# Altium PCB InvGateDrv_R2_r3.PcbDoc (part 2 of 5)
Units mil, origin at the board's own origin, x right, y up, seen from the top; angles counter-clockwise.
Board outline 6245 x 2850 mil, 4 copper layers (Top Layer, Power, Ground, Bottom Layer), stack 104.204 mil thick; 409 components, 181 nets, 1050 pads, 683 vias.
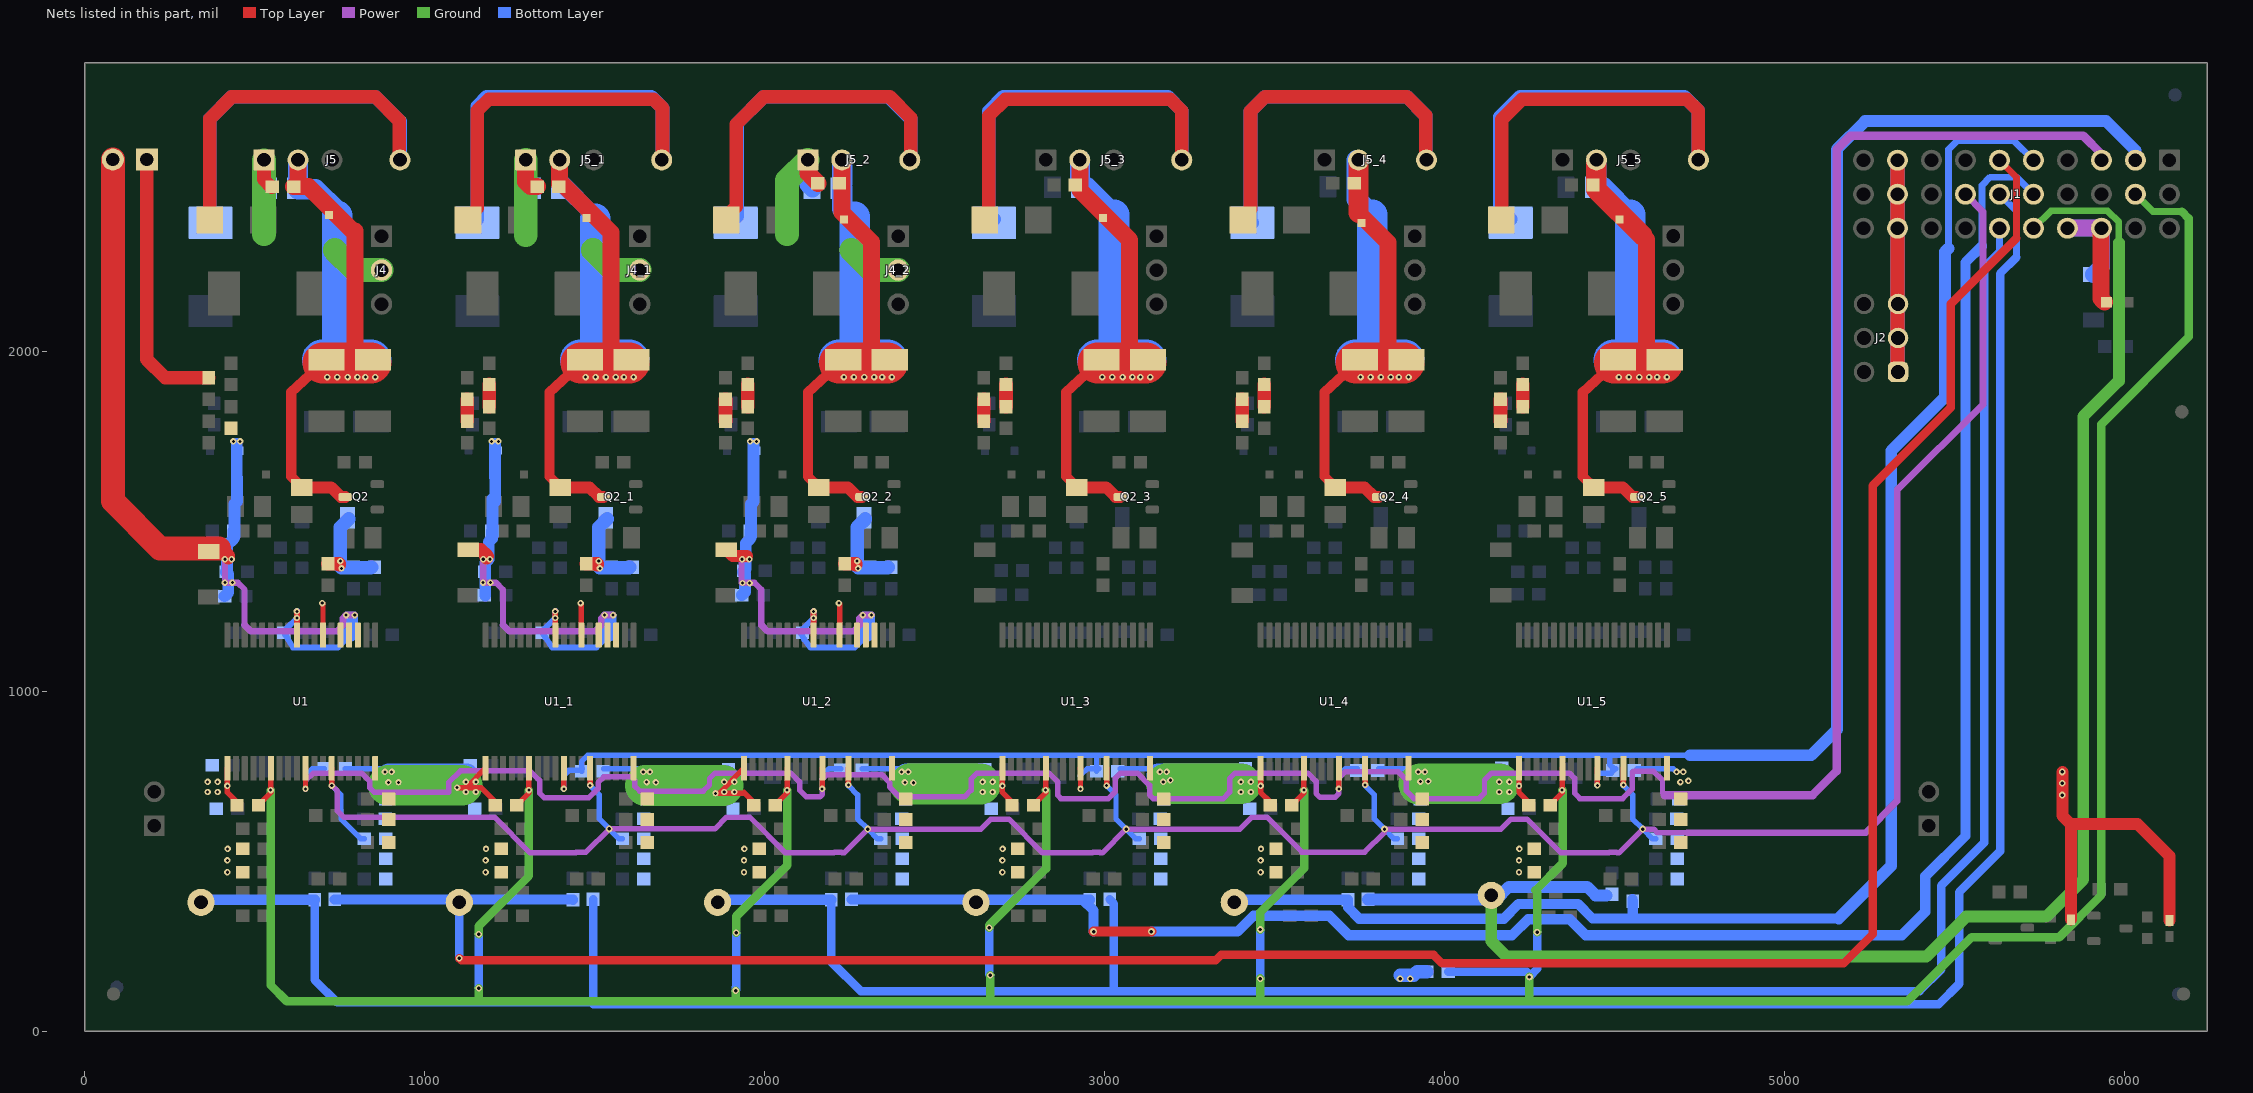
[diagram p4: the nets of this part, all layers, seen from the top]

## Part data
C1: library part CMP-0008658-2, "CAP, CERM, 10 uF, 50 V, +/- 10%, X5R, 1206", Cap_Case=1206_180, Manufacturer=TDK, Supplier Part Number 1=445-5998-1-ND, TempCo=X5R, Tolerance_%=10%, Value1="0.002229 ohm", Value2=50V, ValueDisplayed=10uF
C2 C2_1 C2_2 C2_3 C2_4 C2_5: library part CMP-0007442-5, "CAP, CERM, 220 pF, 50 V, +/- 10%, X7R, 0603", Cap_Case=0603, Manufacturer=MuRata, Supplier Part Number 1=490-1483-1-ND, TempCo=X7R, Tolerance_%=10%, Value1=Unknown, Value2=50V, ValueDisplayed=220pF
C3 C3_1 C3_2 C3_3 C3_4 C3_5 C4 C4_1 C4_2 C4_3 C4_4 C4_5: library part CMP-0008802-2, "CAP, CERM, 10 uF, 50 V, +/- 10%, X7R, 1206", Cap_Case=1206, Manufacturer=Samsung, Supplier Part Number 1=1276-6767-1-ND, TempCo=X7R, Tolerance_%=10%, Value1=Unknown, Value2=50V, ValueDisplayed=10uF
C5 C5_1 C5_2 C5_3 C5_4 C5_5: library part CMP-0007433-4, "CAP, CERM, 0.01 uF, 50 V, +/- 10%, X7R, 0603", Cap_Case=0603, Manufacturer=MuRata, Supplier Part Number 1=490-1512-1-ND, TempCo=X7R, Tolerance_%=10%, Value1=Unknown, Value2=50V, ValueDisplayed=0.01uF
C6 C6_1 C6_2 C6_3 C6_4 C6_5: library part CMP-0007137-5, "CAP, CERM, 1 uF, 16 V, +/- 20%, X7R, AEC-Q200 Grade 1, 0603", Cap_Case=0603, Manufacturer=MuRata, TempCo=X7R, Tolerance_%=20%, Value1=Unknown, Value2=16V, ValueDisplayed=1uF
C7 C7_1 C7_2 C7_3 C7_4 C7_5 C31 C31_1 C31_2 C31_3 C31_4 C31_5: library part CMP-0007106-4, "CAP, CERM, 0.1 uF, 16 V, +/- 10%, X7R, AEC-Q200 Grade 1, 0603", Cap_Case=0603, Manufacturer=TDK, Supplier Part Number 1=445-8136-1-ND, TempCo=X7R, Tolerance_%=10%, Value1=Unknown, Value2=16V, ValueDisplayed=0.1uF
C8 C8_1 C8_2 C8_3 C8_4 C8_5 C9 C9_1 C9_2 C9_3 C9_4 C9_5 C10 C10_1 C10_2 C10_3 C10_4 C10_5 C18 C18_1 C18_2 C18_3 C18_4 C18_5 C19 C19_1 C19_2 C19_3 C19_4 C19_5 C20 C20_1 C20_2 C20_3 C20_4 C20_5 C21 C21_1 C21_2 C21_3 C21_4 C21_5 C22 C22_1 C22_2 C22_3 C22_4 C22_5 C23 C23_1 C23_2 C23_3 C23_4 C23_5 C24 C24_1 C24_2 C24_3 C24_4 C24_5 C25 C25_1 C25_2 C25_3 C25_4 C25_5 C26 C26_1 C26_2 C26_3 C26_4 C26_5: library part CMP-0750041-1, "CAP, CERM, 100 pF, 50 V,+/- 5%, C0G/NP0, AEC-Q200 Grade 1, 0603", Cap_Case=0603, Manufacturer=MuRata, TempCo=C0G/NP0, Tolerance_%=5%, Value2=50V, ValueDisplayed=100pF
C11 C11_1 C11_2 C11_3 C11_4 C11_5 C13 C13_1 C13_2 C13_3 C13_4 C13_5 C15 C15_1 C15_2 C15_3 C15_4 C15_5 C29 C29_1 C29_2 C29_3 C29_4 C29_5: library part CMP-0007010-5, "CAP, CERM, 0.1 uF, 50 V, +/- 10%, X5R, 0603", Cap_Case=0603, Manufacturer=TDK, Supplier Part Number 1=445-7456-1-ND, TempCo=X5R, Tolerance_%=10%, Value1="0.0296 ohm", Value2=50V, ValueDisplayed=0.1uF
C12 C12_1 C12_2 C12_3 C12_4 C12_5 C14 C14_1 C14_2 C14_3 C14_4 C14_5 C17 C17_1 C17_2 C17_3 C17_4 C17_5 C30 C30_1 C30_2 C30_3 C30_4 C30_5: library part CMP-0007067-4, "CAP, CERM, 1 uF, 35 V, +/- 10%, X7R, AEC-Q200 Grade 1, 0603", Cap_Case=0603, Manufacturer=TDK, Supplier Part Number 1=445-174215-1-ND, TempCo=X7R, Tolerance_%=10%, Value1="0.005522 ohm", Value2=35V, ValueDisplayed=1uF
C16 C16_1 C16_2 C16_3 C16_4 C16_5: library part CMP-0007725-2, "CAP, CERM, 0.1 uF, 50 V, +/- 10%, X7R, AEC-Q200 Grade 0, 0805", Cap_Case=0805, Manufacturer=Kemet, Supplier Part Number 1=399-6928-1-ND, TempCo=X7R, Tolerance_%=10%, Value1=Unknown, Value2=50V, ValueDisplayed=0.1uF
C27 C27_1 C27_2 C27_3 C27_4 C27_5 C28 C28_1 C28_2 C28_3 C28_4 C28_5: library part CMP-0007112-4, "CAP, CERM, 4.7 uF, 6.3 V, +/- 10%, X7R, 0603", Cap_Case=0603, Manufacturer=Samsung, Supplier Part Number 1=1276-2087-1-ND, TempCo=X7R, Tolerance_%=10%, Value1=Unknown, Value2=6.3V, ValueDisplayed=4.7uF
D1 D13: library part CMP-0002947-3, "LED, Red, SMD", Color=Red, Manufacturer="Wurth Elektronik", Power_TotalModule=72mW, Value1=0.072W, Value2=2V
D2: library part CMP-0002905-2, "LED, Green, SMD", Color=Green, Manufacturer="Wurth Elektronik", Value1=W, Value2=3.2V
D3 D3_1 D3_2 D3_3 D3_4 D3_5: library part CMP-0077081-2, "Diode, Ultrafast, 1200 V, 1 A, SMA", Manufacturer=STMicroelectronics, Value1=1A, Value2=1.9V
D5 D5_1 D5_2 D5_3 D5_4 D5_5 D10 D10_1 D10_2 D10_3 D10_4 D10_5: library part CMP-0028458-2, "Diode, Schottky, 30 V, 0.2 A, SOD-323", Manufacturer="Diodes Inc.", Value1=0.2A, Value2=0.7V
D7 D7_1 D7_2 D7_3 D7_4 D7_5 D8 D8_1 D8_2 D8_3 D8_4 D8_5: library part CMP-0088475-1, "486V Clamp 3.1A Ipp Tvs Diode Surface Mount DO-214AB (SMCJ)", Breakdown Voltage=335V, Clamping Voltage=486V, Digikey Part Number=SMCJ300ALFCT-ND, Manufacturer="Littelfuse Inc", Mouser Part Number=576-SMCJ300A, Operating Temperature Range="-65°C to +150°C"
D9 D9_1 D9_2 D9_3 D9_4 D9_5: library part CMP-0005831-4, "Diode, Zener, 12 V, 200 mW, SOD-323", Manufacturer="Diodes Inc.", Power_W=200mW, Value1=0.2W
FID1 FID2 FID3 FID4 FID5 FID6: library part CMP-0077181-1, "Fiducial mark.  There is nothing to buy or mount.", Manufacturer=N/A
"High Voltage1" "High Voltage2": library part CMP-0074835-1, "IEC 61010-1 High Voltage Warning"
J1: library part CMP-0088701-1, "Conn Unshrouded Header HDR 30 POS 2.54mm Solder RA Thru-Hole Automotive Bulk", Current_A=6.3A, Digikey Part Number=TSW-110-08-G-T-RA-ND, Manufacturer=Samtec, Mouser Part Number=200-TSW11008GTRA, Operating Temperature Range="-55°C to +125°C", Voltage_V=450V
J2: library part CMP-0082513-1, "Receptacle, 2.54mm, 3x2, Gold, TH", Color=Black, Current_A=3A, Manufacturer="Sullins Connector Solutions", Supplier Part Number 1=S7106-ND, Voltage_V=250V
J3 J6: library part CMP-0055684-1, "Receptacle, 2.54mm, 2x1, Gold, TH", Color=Black, Current_A=6.3A, Manufacturer=Samtec, Supplier Part Number 1=SAM1198-02-ND
J4 J4_1 J4_2 J4_3 J4_4 J4_5: library part CMP-0054646-1, "Receptacle, 100mil, 3x1, Gold, TH", Manufacturer="Sullins Connector Solutions", Supplier Part Number 1=S7036-ND
J5 J5_1 J5_3 J5_5: library part CMP-0088430-1, "THROUGH-HOLE .025\" SQ POST HEADER", Digikey Part Number=TSW-105-08-G-S-RA-004-ND, Manufacturer=Samtec, Mouser Part Number=200-TSW10508GSRA004, Operating Temperature Range="-55°C to +125°C", Voltage_V=550V
J5_2 J5_4: library part CMP-0088429-1, "Conn Unshrouded Header HDR 4 POS 2.54mm Solder RA Thru-Hole Automotive Bulk", Digikey Part Number=TSW-104-08-G-S-RA-003-ND, Manufacturer=Samtec, Mouser Part Number=200-TSW10408GSRA003, Operating Temperature Range="-55°C to +125°C", Voltage_V=550V
J7: library part CMP-0055976-1, "Header, 100mil, 2x1, Gold, R/A, TH", Color=Black, Current_A=6.3A, Manufacturer=Samtec, Supplier Part Number 1=SAM1039-02-ND, Voltage_V=550V
Logo1: library part CMP-0074844-1
Logo3: library part CMP-0074769-1
PWM_1 PWM_2 PWM_3 PWM_4 PWM_5 PWM_6: library part CMP-0055139-1, "Test Point, Miniature, White, TH", Color=White, Manufacturer=Keystone, Supplier Part Number 1=36-5002-ND
Q1 Q3: library part CMP-0000314-2, "Transistor, PNP, 65 V, 0.01 A, SOT-23", Manufacturer="Diodes Inc.", Supplier Part Number 1=BC856A-FDICT-ND, Value1="0.01 A"
Q2 Q2_1 Q2_2 Q2_3 Q2_4 Q2_5: library part CMP-0000739-1, "MOSFET, N-CH, 40 V, 5.6 A, SOT-23", Alternate Manufacturer=None, Manufacturer=Vishay-Siliconix, Supplier Part Number 1=SI2318CDS-T1-GE3CT-ND, Value1=0.05, Value2="5.8 nC"
R1 R29: library part CMP-0022691-3, "RES, 20.0 k, 1%, 0.1 W, AEC-Q200 Grade 0, 0603", Manufacturer=Panasonic, Power_W=100mW, Supplier Part Number 1=P20.0KHCT-ND, TempCo="100 ppm/C", Tolerance_%=1%, Value2=0.1W, Value_Code=20k0, ValueDisplayed=20.0k
R2 R12 R12_1 R12_2 R12_3 R12_4 R12_5: library part CMP-0025701-4, "RES, 10 k, 5%, 0.1 W, AEC-Q200 Grade 0, 0603", Manufacturer=Vishay-Dale, Power_W=100mW, Supplier Part Number 1=541-10KGCT-ND, TempCo="200 ppm/C", Tolerance_%=5%, Value2=0.1W, Value_Code=10k0, ValueDisplayed=10k
R3 R30: library part CMP-0026833-3, "RES, 120, 5%, 0.063 W, AEC-Q200 Grade 0, 0402", Manufacturer=Vishay-Dale, Power_W=63mW, Supplier Part Number 1=541-120JCT-ND, TempCo="200 ppm/C", Tolerance_%=5%, Value2=0.063W, Value_Code=120R, ValueDisplayed=120
R4 R4_1 R4_2 R4_3 R4_4 R4_5 R18 R18_1 R18_2 R18_3 R18_4 R18_5 R21 R21_1 R21_2 R21_3 R21_4 R21_5: library part CMP-0022109-5, "RES, 1.00 k, 1%, 0.1 W, AEC-Q200 Grade 0, 0603", Manufacturer=Vishay-Dale, Power_W=100mW, Supplier Part Number 1=541-1.00KHCT-ND, TempCo="100 ppm/C", Tolerance_%=1%, Value2=0.1W, Value_Code=1k00, ValueDisplayed=1.00k
R7 R7_1 R7_2 R7_3 R7_4 R7_5: library part CMP-0020847-3, "RES, 10.0, 1%, 0.125 W, AEC-Q200 Grade 0, 0805", Manufacturer=Vishay-Dale, Power_W=125mW, Supplier Part Number 1=541-10.0CCT-ND, TempCo="100 ppm/C", Tolerance_%=1%, Value2=0.125W, Value_Code=10R0, ValueDisplayed=10.0
R8 R8_1 R8_2 R8_3 R8_4 R8_5: "RES, 10, 5%, 0.125 W, 0805", Manufacturer=Vishay-Dale, Power_W=0.125, Supplier Part Number 1=541-10ACT-ND, TempCo="200 ppm/C", Tolerance_%=5, Value1=5%, Value2=0.125W, Value_Code=10R0, ValueDisplayed=10
R9 R9_1 R9_2 R9_3 R9_4 R9_5 R10 R10_1 R10_2 R10_3 R10_4 R10_5 R11 R11_1 R11_2 R11_3 R11_4 R11_5: library part CMP-0022684-3, "RES, 10.0 k, 1%, 0.1 W, 0603", Manufacturer=Panasonic, Power_W=100mW, Supplier Part Number 1=P10.0KHCT-ND, TempCo="100 ppm/C", Tolerance_%=1%, Value2=0.1W, Value_Code=10k0, ValueDisplayed=10.0k
R13 R13_1 R13_2 R13_3 R13_4 R13_5 R14 R14_1 R14_2 R14_3 R14_4 R14_5 R17 R17_1 R17_2 R17_3 R17_4 R17_5 R19 R19_1 R19_2 R19_3 R19_4 R19_5: library part CMP-0025700-4, "RES, 100, 5%, 0.1 W, AEC-Q200 Grade 0, 0603", Manufacturer=Vishay-Dale, Power_W=100mW, Supplier Part Number 1=541-100GCT-ND, TempCo="200 ppm/C", Tolerance_%=5%, Value2=0.1W, Value_Code=100R, ValueDisplayed=100
R15 R15_1 R15_2 R15_3 R15_4 R15_5 R16 R16_1 R16_2 R16_3 R16_4 R16_5: "RES, 0, 5%, 0.125 W, 0805", Manufacturer=Vishay-Dale, Power_W=0.125, Supplier Part Number 1=541-0.0ACT-ND, TempCo="200 ppm/C", Tolerance_%=5, Value1=5%, Value2=0.125W, Value_Code=0000, ValueDisplayed=0
R20 R20_1 R20_2 R20_3 R20_4 R20_5: "RES, 10.0 k, 1%, 0.1 W, 0603", Manufacturer="Vishay Draloric", Power_W=0.1, Supplier Part Number 1=541-1784-1-ND, TempCo="100 ppm/C", Tolerance_%=1, Value1=1%, Value2=0.1W, Value_Code=10k0, ValueDisplayed=10.0k
R22 R22_1 R22_2 R22_3 R22_4 R22_5 R25 R25_1 R25_2 R25_3 R25_4 R25_5: library part CMP-0025697-4, "RES, 0, 5%, 0.1 W, AEC-Q200 Grade 0, 0603", Manufacturer=Vishay-Dale, Power_W=100mW, Supplier Part Number 1=541-0.0GCT-ND, TempCo="200 ppm/C", Tolerance_%=5%, Value2=0.1W, Value_Code=0000, ValueDisplayed=0
R23 R23_1 R23_2 R23_3 R23_4 R23_5 R24 R24_1 R24_2 R24_3 R24_4 R24_5 R26 R26_1 R26_2 R26_3 R26_4 R26_5 R28 R28_1 R28_2 R28_3 R28_4 R28_5: "RES, 10, 5%, 0.75 W, AEC-Q200 Grade 0, 2010", Manufacturer=Vishay-Dale, Power_W=0.75, Supplier Part Number 1=541-10.0WCT-ND, TempCo="200 ppm/C", Tolerance_%=5, Value1=5%, Value2=0.75W, Value_Code=10R0, ValueDisplayed=10
R27: library part CMP-0023219-5, "RES, 620, 1%, 0.1 W, 0603", Manufacturer=Yageo, Power_W=100mW, Supplier Part Number 1=311-620HRCT-ND, TempCo="100 ppm/C", Tolerance_%=1%, Value2=0.1W, Value_Code=620R, ValueDisplayed=620
U1 U1_1 U1_2 U1_3 U1_4 U1_5: library part CMP-0080759-3, "Isolated IGBT, SiC MOSFET Gate Driver With Real-Time Programmability, DWJ0036A (SOIC-36)", Alternate Manufacturer="Texas Instruments"
ZZ1: library part CMP-0003616-3
ZZ2: library part CMP-0077236-1
ZZ3: library part CMP-0077237-1
ZZ4: library part CMP-0077238-1

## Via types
v1: diameter 19, hole 9, Top Layer to Bottom Layer, tented both sides, 617 vias
v2: diameter 20, hole 10, Top Layer to Bottom Layer, tented both sides, 66 vias

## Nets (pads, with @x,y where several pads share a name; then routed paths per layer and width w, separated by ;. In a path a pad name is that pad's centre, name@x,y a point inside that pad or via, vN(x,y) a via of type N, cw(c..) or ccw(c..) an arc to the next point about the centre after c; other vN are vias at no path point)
Al1: J7.1 R22.2 | length 792.7
  Top Layer w40: J7.1@183.03,2565 183.03,1976.97 236.97,1923.03 R22.2@365.39,1923.03
Al1_1: R18_1.2 R22_1.1 | length 65
  Top Layer w40: R18_1.2@1125.39,1795.08 R22_1.1@1125.39,1860.04
Al1_2: R18_2.2 R22_2.1 | length 65
  Top Layer w40: R18_2.2@1885.39,1795.08 R22_2.1@1885.39,1860.04
Al1_3: R18_3.2 R22_3.1 | length 65
  Top Layer w40: R18_3.2@2645.39,1795.08 R22_3.1@2645.39,1860.04
Al1_4: R18_4.2 R22_4.1 | length 65
  Top Layer w40: R18_4.2@3405.39,1795.08 R22_4.1@3405.39,1860.04
Al1_5: R18_5.2 R22_5.1 | length 65
  Top Layer w40: R18_5.2@4165.39,1795.08 R22_5.1@4165.39,1860.04
Al3: R25.2
Al3_1: R21_1.2 R25_1.1 | length 65.9
  Top Layer w40: R25_1.1@1190.51,1837.17 R21_1.2@1190.51,1903.11
Al3_2: R21_2.2 R25_2.1 | length 65.9
  Top Layer w40: R25_2.1@1950.51,1837.16 R21_2.2@1950.51,1903.11
Al3_3: R21_3.2 R25_3.1 | length 65.9
  Top Layer w40: R25_3.1@2710.51,1837.17 R21_3.2@2710.51,1903.11
Al3_4: R21_4.2 R25_4.1 | length 65.9
  Top Layer w40: R25_4.1@3470.51,1837.16 R21_4.2@3470.51,1903.11
Al3_5: R21_5.2 R25_5.1 | length 65.9
  Top Layer w40: R25_5.1@4230.51,1837.17 R21_5.2@4230.51,1903.12
ASC: C24.1 C24_2.1 C24_4.1 J1.7 U1.10 U1_2.10 U1_4.10 | length 8723
  Top Layer w16: v1(649.78,713.6) 649.78,773.8 U1.10@650.16,774.17 ; v1(2169.78,713.6) 2169.78,773.8 U1_2.10@2170.16,774.17 ; v1(3689.78,713.6) 3689.78,773.8 U1_4.10@3690.16,774.17
  Power w16: v1(649.78,713.6) 649.78,737.2 650.16,737.57 672.58,760 814.29,760 838.35,735.94 838.35,717.32 852.38,703.29 1071.64,703.29 1071.64,706.36 1071.13,706.88 1071.13,732.39 1105.36,766.63 1310.03,766.63 1338.35,738.3 1338.35,700.63 1351.49,687.48 1483.21,687.48 1496.2,700.48 1496.63,700.48 1510.39,714.24 1510.39,731.7 1527.78,749.08 1608.48,749.08 1618.35,739.21 1618.35,721.35 1633.13,706.57 1819.92,706.57 1838.35,725 1838.35,743.35 1855,760 2077.37,760 2103.35,734.02 2103.35,710 2123.35,690 2163.35,690 2170.16,696.81 2169.78,697.18 v1(2169.78,713.6) 2169.78,741.44 2170.16,741.81 2183.35,755 2345.12,755 2368.47,731.65 2368.47,719.5 2397.97,690 2588.35,690 2608.35,710 2608.35,742.91 2625.43,760 2836.46,760 2863.35,733.11 2863.35,693.87 2872.22,685 3011.77,685 3032.52,705.75 3032.52,744.84 3047.68,760 3097.26,760 3133.35,723.91 3133.35,695.39 3143.74,685 3349.8,685 3368.35,703.54 3368.35,743.35 3385,760 3598.65,760 3623.35,735.31 3623.35,700 3634.8,688.54 3678.7,688.54 3690.16,700 3689.78,700.37 v1(3689.78,713.6) 3689.78,744.94 3690.16,745.31 3708.19,763.35 3864.84,763.35 3888.35,739.84 3888.35,707.32 3910.67,685 4102.6,685 4118.35,700.75 4118.35,739.46 4138.89,760 4367.92,760 4383.35,744.57 4383.35,700.63 4398.97,685 4524.92,685 4552.52,712.59 4552.52,761.46 4556.06,765 4615.93,765 4642.08,738.85 4642.08,701.26 4648.35,695
  Power w25: 4648.35,695 5083.35,695 5154.17,765.83 ; 5155,765.83 5155,2550 5155,2595 5195,2635 5880,2635 5933.35,2581.65 J1.7@5933.35,2562.88
  Bottom Layer w16: v1(649.78,713.6) 649.78,753.13 650.16,753.5 669.84,773.19 C24.1@704.29,773.19 ; v1(2169.78,713.6) 2169.78,753.13 2170.16,753.5 2189.84,773.19 C24_2.1@2224.29,773.19 ; v1(3689.78,713.6) 3689.78,753.13 3690.16,753.5 3709.84,773.19 C24_4.1@3744.29,773.19
ASC_1: C24_1.1 C24_3.1 C24_5.1 J1.4 U1_1.10 U1_3.10 U1_5.10 | length 7011.7
  Top Layer w16: v1(1409.78,713.6) 1409.78,773.8 U1_1.10@1410.15,774.18 ; v1(2929.78,713.6) 2929.78,772.23 2929,773.02 U1_3.10@2930.16,774.17 ; v1(4450.15,723.98) U1_5.10@4450.15,774.18
  Bottom Layer w16: v1(1409.78,713.6) 1409.78,753.13 1424.52,767.88 1458.97,767.88 C24_1.1@1461.85,770.75 ; C24_1.1@1461.85,765 C24_1.1@1461.85,770.75 ; C24_1.1@1464.29,773.19 C24_1.1@1461.85,770.75 ; v1(2929.78,713.6) 2929.78,751.56 2929,752.35 2949.84,773.19 C24_3.1@2976.85,773.19 ; C24_3.1@2976.85,765 C24_3.1@2976.85,773.19 ; C24_3.1@2984.29,773.19 C24_3.1@2976.85,773.19 ; v1(4450.15,723.98) 4450.15,753.51 4456.65,760 4491.09,760 C24_5.1@4504.29,773.19 ; C24_5.1@4495.43,767.29 4495.43,776.61 4486.49,785.55 4486.49,812.37 ; 4723.35,812.37 4486.49,812.37 ; C24_1.1@1461.85,770.75 1461.85,793.6 1480.63,812.37 2975.04,812.37 ; 2975.04,812.37 4486.49,812.37 ; 2975.04,812.37 2976.85,810.56 C24_3.1@2976.85,773.19
  Bottom Layer w35: 4723.35,812.37 5079.75,812.37 5155,887.63 5155,2560 5155,2595 5238,2678 5947,2678 6033.35,2591.65 J1.4@6033.35,2562.88
ASC_EN: C10.2 C10_1.2 C10_2.2 C10_3.2 C10_4.2 C10_5.2 J1.5 R2.2 U1.6 U1_1.6 U1_2.6 U1_3.6 U1_4.6 U1_5.6 | length 12755.2
  Top Layer w16: C10.2@511.38,674.76 520.24,674.76 546.94,701.46 v1(546.94,710) 546.94,773.32 U1.6@547.8,774.17 ; C10_1.2@1271.37,674.77 1280.23,674.77 1306.93,701.47 v1(1306.93,710) 1306.93,773.32 U1_1.6@1307.79,774.18 ; C10_2.2@2031.38,674.76 2040.24,674.76 2066.94,701.46 v1(2066.94,710) 2066.94,773.31 U1_2.6@2067.8,774.17 ; C10_3.2@2791.38,674.76 2800.24,674.76 2826.94,701.46 v1(2826.94,710) 2826.94,773.32 U1_3.6@2827.8,774.17 ; C10_4.2@3551.38,674.76 3560.24,674.76 3586.94,701.46 v1(3586.94,710) 3586.94,773.31 U1_4.6@3587.8,774.17 ; C10_5.2@4311.37,674.77 4320.23,674.77 4346.93,701.47 v1(4346.93,710) 4346.93,773.32 U1_5.6@4347.79,774.18
  Ground w20: J1.5@6033.35,2462.88 6084.51,2411.72 6170,2411.72
  Ground w25: v1(546.94,710) 546.94,136.41 594.73,88.62 2663.35,88.62 ; 1159.48,95 v2(1159.48,126.66) ; v2(1159.48,285.69) 1159.48,309.91 1306.93,457.36 v1(1306.93,710) ; 1915.37,95 v2(1915.37,120) ; v2(1917.23,290.11) 1917.23,338.5 2066.94,488.2 v1(2066.94,710) ; v2(2661.46,305) 2661.46,312.27 2828.35,479.15 2828.35,708.59 v1(2826.94,710) ; v2(2664.08,165) 2664.08,89.35 2663.35,88.62 ; 3458.35,93.02 v2(3458.35,155) v2@3458.35,156.45 ; v2(3458.35,299.62) 3458.08,299.89 3458.08,350 3588.35,480.26 3588.35,708.59 v1(3586.94,710) ; v2@4250.13,160 4250.13,92.58 4246.17,88.62 ; v2(4273.16,291.8) 4273.16,409.67 4268.35,414.49 4348.35,494.49 4348.35,708.59 v1(4346.93,710) ; 6170,2411.72 6190,2391.72 6190,2042.91 5933.35,1786.25 5933.35,401.44 5809.03,277.13 5551.23,277.13 5362.72,88.62 4246.17,88.62 ; 2663.35,88.62 4246.17,88.62
  Bottom Layer w25: v2(1159.48,126.66) v2(1159.48,285.69) ; 1915.37,130.53 v2(1915.37,120) 1917.23,121.86 v2(1917.23,290.11) ; v2(2661.46,305) 2661.46,167.62 v2(2664.08,165) ; v2(3458.35,155) v2(3458.35,299.62) ; R2.2@4011.5,175 4242.19,175 v2@4253.35,163.84 ; v2@4249.51,160 v2@4253.35,163.84 ; v2(4273.16,291.8) 4273.16,183.65 v2@4253.35,163.84
  other v2: 4250.39,160
CLK: C20.1 C20_1.1 C20_2.1 C20_3.1 C20_4.1 C20_5.1 J1.20 U1.13 U1_1.13 U1_2.13 U1_3.13 U1_4.13 U1_5.13 | length 8570.3
  Top Layer w16: U1.13@726.93,774.17 726.93,724.96 727,724.89 v1(727,722.92) ; v1(1486.89,723.98) 1486.89,724.93 U1_1.13@1486.92,774.18 ; v1(2246.93,724.96) U1_2.13@2246.93,774.17 ; v1(3006.93,722.99) 3006.93,724.96 U1_3.13@3006.93,774.17 ; v1(3766.93,724.96) U1_4.13@3766.93,774.17 ; v1(4526.93,724.97) U1_5.13@4526.93,774.18
  Power w16: v1(727,722.92) 743.35,706.57 743.35,648.94 762.28,630 1205.83,630 1310.83,525 1444.41,525 1446.52,527.11 1474.88,527.11 v2(1543.44,595.68) 1854.38,595.68 1888.71,630 1956.73,630 2061.73,525 2204.42,525 2206.53,527.11 2226.31,527.11 2228.42,525 2234.12,525 v2(2304.12,595) 2636.81,595 2666.38,624.57 2718.78,624.57 2818.35,525 2964.42,525 2966.53,527.11 2986.31,527.11 2988.42,525 2994.12,525 v2(3064.12,595) 3398.78,595 3433.78,630 3478.35,630 3581.24,527.11 3765.46,527.11 3824.12,585.77 v2(3824.12,595) 4166.81,595 4196.38,624.57 4243.35,624.57 4342.92,525 4484.41,525 4486.53,527.11 4506.3,527.11 4508.42,525 4514.12,525 v2(4584.12,595) 4616.82,595 4627.6,584.22 4714.92,584.22
  Power w20: 4714.92,584.22 5239.22,584.22 5332.5,677.5 5332.5,1592.5 5584.57,1844.57 5584.57,2383.52 5585,2383.95 5585,2411.23 J1.20@5533.35,2462.88
  Bottom Layer w16: v1(727,722.92) 754.27,695.65 754.27,624.85 812.62,566.5 C20.1@822.4,566.5 ; v1(1486.89,723.98) 1486.89,723.02 1514.26,695.66 1514.26,624.85 1572.62,566.5 C20_1.1@1582.4,566.5 ; v1(2246.93,724.96) 2246.93,722.99 2274.27,695.65 2274.27,624.85 v2(2304.12,595) 2332.62,566.5 C20_2.1@2342.4,566.5 ; v1(3006.93,722.99) 3034.27,695.65 3034.27,624.85 v2(3064.12,595) 3092.62,566.5 C20_3.1@3102.4,566.5 ; v1(3766.93,724.96) 3766.93,722.99 3794.27,695.65 3794.27,624.85 v2(3824.12,595) 3852.62,566.5 C20_4.1@3862.4,566.5 ; v1(4526.93,724.97) 4526.93,723 4554.26,695.66 4554.26,624.85 v2(4584.12,595) 4612.62,566.5 C20_5.1@4622.4,566.5
GND: C1.2 C6.2 C6_1.2 C6_2.2 C6_3.2 C6_4.2 C6_5.2 C7.2 C7_1.2 C7_2.2 C7_3.2 C7_4.2 C7_5.2 C8.1 C8_1.1 C8_2.1 C8_3.1 C8_4.1 C8_5.1 C9.1 C9_1.1 C9_2.1 C9_3.1 C9_4.1 C9_5.1 C10.1 C10_1.1 C10_2.1 C10_3.1 C10_4.1 C10_5.1 C20.2 C20_1.2 C20_2.2 C20_3.2 C20_4.2 C20_5.2 C21.2 C21_1.2 C21_2.2 C21_3.2 C21_4.2 C21_5.2 C22.2 C22_1.2 C22_2.2 C22_3.2 C22_4.2 C22_5.2 C23.2 C23_1.2 C23_2.2 C23_3.2 C23_4.2 C23_5.2 C24.2 C24_1.2 C24_2.2 C24_3.2 C24_4.2 C24_5.2 C25.2 C25_1.2 C25_2.2 C25_3.2 C25_4.2 C25_5.2 C26.2 C26_1.2 C26_2.2 C26_3.2 C26_4.2 C26_5.2 C27.2 C27_1.2 C27_2.2 C27_3.2 C27_4.2 C27_5.2 C31.2 C31_1.2 C31_2.2 C31_3.2 C31_4.2 C31_5.2 D2.1 J1.9 J1.12 R2.1 R3.1 R30.1 U1.1 U1.18 U1_1.1 U1_1.18 U1_2.1 U1_2.18 U1_3.1 U1_3.18 U1_4.1 U1_4.18 U1_5.1 U1_5.18 | length 5489.4
  Top Layer w16: U1.1@419.84,774.17 v1(419.84,722) 419.84,703.31 C10.1@448.39,674.76 ; v1(1096,717.18) 1122.84,717.18 ; U1_1.1@1179.84,774.18 1122.84,717.18 ; C10_1.1@1208.38,674.77 1165.97,717.18 1122.84,717.18 ; v1(1856,700) 1865.67,700 ; U1_2.1@1939.84,774.17 1865.67,700 ; C10_2.1@1968.39,674.76 1939.84,703.31 1936.54,700 1865.67,700 ; U1_3.1@2699.84,774.17 v1(2699.84,722) 2699.84,703.31 C10_3.1@2728.39,674.76 ; U1_4.1@3459.84,774.17 v1(3459.84,722) 3459.84,703.31 C10_4.1@3488.39,674.76 ; U1_5.1@4219.84,774.18 v1(4219.84,722) 4219.84,703.31 C10_5.1@4248.38,674.77
  Top Layer w35: v2(5818.35,763.35) v2(5818.35,730) v2(5818.35,695) 5818.35,635 5843.35,610 ; R30.1@5843.35,328.62 5843.35,610 ; R3.1@6133.35,326.44 6133.35,516.39 6039.74,610 5843.35,610
  Top Layer w50: J1.9@5932.6,2362.88 5932.6,2155.43 D2.1@5941.85,2146.18
  Power w50: J1.12@5833.35,2362.88 J1.9@5933.35,2362.88
  Ground w120: v1@893.35,723.97 1109.87,723.97 ; 1650.39,723.62 1878.35,723.62 ; 2427.8,727.72 v1@2635.18,727.72 ; 3182.16,728.55 v1@3401.77,728.55 ; v1@3925,727.01 3926.25,727.11 3930.43,727.44 3943.11,728.42 v1@4161.77,728.42
  Bottom Layer w16: C24.2@767.28,773.19 873.58,773.19 v1(883.43,763.35) ; C24_1.2@1527.28,773.19 1633.58,773.19 v1(1643.42,763.35) ; C24_2.2@2287.28,773.19 2393.58,773.19 v1(2403.43,763.35) ; C24_3.2@3047.28,773.19 3153.58,773.19 v1(3163.43,763.35) ; C24_4.2@3807.28,773.19 3913.58,773.19 v1(3923.42,763.35) ; C24_5.2@4567.28,773.19 4673.58,773.19 v1(4683.42,763.35)
  Bottom Layer w40: 3870,165 3910,165 3920,175 R2.1@3948.5,175
  Bottom Layer w50: J1.12@5833.35,2362.88 J1.9@5933.35,2362.88 5933.35,2250.28 C1.2@5910,2226.93
  Bottom Layer w70: 895.24,753.5 1123.19,753.5 ; 1652.22,749.33 1883.44,749.33 ; 2417.22,753.5 C7_3.2@2636.59,753.5 ; 3158.35,753.5 3403.19,753.5 ; 3920.49,747.43 4158.35,747.43
  other v1: 419.84,468.07 1179.84,468.07 1939.84,468.07 2699.84,468.07 3459.84,468.07 4219.84,468.08 419.84,503.24 1179.84,503.24 1939.84,503.24 2699.84,503.24 3459.84,503.24 4219.84,503.24 420.83,536.97 1180.82,536.97 1940.83,536.97 2700.83,536.97 3460.83,536.97 4220.82,536.97 361.77,704.29 391.3,704.29 1121.77,704.29 1151.3,704.29 1881.77,704.29 1911.3,704.29 2641.77,704.29 2671.3,704.29 3401.77,704.29 3431.3,704.29 4161.77,704.3 4191.3,704.3 2438.35,731.41 893.35,732.59 923.35,732.59 1653.35,733.39 1680.53,732.59 2413.27,732.59 4694.55,733.18 361.77,733.82 391.3,733.82 1121.77,733.82 1151.3,733.82 1881.77,733.82 1911.3,733.82 2641.77,733.82 2671.3,733.82 3173.27,734.02 3401.77,733.82 3431.3,733.82 4161.77,733.82 4191.3,733.82 3929.84,735 3952.95,735.56 4718.35,736.77 3193.94,738.76 903.11,763.35 1663.11,763.35 2423.11,763.35 3183.11,763.35 3943.11,763.35 4703.11,763.35
  other v2: 3869.96,155 3900,155
GND2: J1.25 J1.26 J1.27 J2.1 J2.3 J2.5 | length 2494.3
  Top Layer w40: J1.25@5333.35,2562.88 J1.26@5333.35,2462.88 J1.27@5333.35,2362.88 5333.35,1941.65 J2.1@5335,1940
  Power w40: J1.25@5333.35,2562.88 J1.26@5333.35,2462.88 J1.27@5333.35,2362.88 5333.35,1941.65 J2.1@5335,1940
  Ground w40: J1.25@5333.35,2562.88 J1.26@5333.35,2462.88 J1.27@5333.35,2362.88 5333.35,1941.65 J2.1@5335,1940
  Bottom Layer w40: J1.25@5333.35,2562.88 J1.26@5333.35,2462.88 J1.27@5333.35,2362.88 5333.35,1941.65 J2.1@5335,1940
IGBT_C: D3.1 D8.1 J5.5 | length 2017.6
  Top Layer w40: D3.1@367.87,2387.36 367.87,2684.53 433.35,2750 855,2750 925,2680 J5.5@925,2562.87
  Bottom Layer w40: D8.1@367.87,2425 367.87,2684.53 433.35,2750 855,2750 927.68,2677.32 J5.5@927.68,2563.82
IGBT_C_1: D3_1.1 D8_1.1 J5_1.5 | length 2130.9
  Top Layer w40: D3_1.1@1113.35,2380 1155,2421.65 1155,2708.82 1188.82,2742.64 1673.54,2742.64 1700,2716.18 1700,2570.55 J5_1.5@1707.67,2562.88
  Bottom Layer w40: D8_1.1@1155.35,2389.43 1155.35,2722 1183.35,2750 1666.18,2750 1700,2716.18 1700,2571.49 J5_1.5@1707.67,2563.82
IGBT_C_2: D3_2.1 D8_2.1 J5_2.4 | length 1960.2
  Top Layer w40: D3_2.1@1877.87,2387.36 1917.23,2426.72 1917.23,2668.85 1998.39,2750 2368.11,2750 2430,2688.11 J5_2.4@2430,2562.87
  Bottom Layer w40: D8_2.1@1920,2397.99 1920,2671.61 1998.39,2750 2365,2750 2430,2685 J5_2.4@2430,2562.87
IGBT_C_3: D3_3.1 D8_3.1 J5_3.5 | length 2144.6
  Top Layer w40: D3_3.1@2633.35,2380 2660,2406.65 2660,2693.81 2708.82,2742.64 3193.55,2742.64 3227.68,2708.5 J5_3.5@3227.68,2563.82 J5_3.5@3227.68,2562.87
  Bottom Layer w40: D8_3.1@2675.35,2389.43 2660,2404.78 2660,2706.65 2703.35,2750 3186.18,2750 3227.68,2708.5 J5_3.5@3227.68,2563.82 J5_3.5@3227.68,2562.87
IGBT_C_4: D3_4.1 D8_4.1 J5_4.4 | length 2038.2
  Top Layer w40: D3_4.1@3397.87,2387.36 3430,2419.49 3430,2706.65 3473.35,2750 3889.84,2750 3945,2694.84 J5_4.4@3945,2562.87
  Bottom Layer w40: D8_4.1@3435.35,2378.86 3430,2384.21 3430,2706.65 3473.35,2750 3889.84,2750 3945,2694.84 J5_4.4@3945,2562.87
IGBT_C_5: D3_5.1 D8_5.1 J5_5.5 | length 2158.3
  Top Layer w40: D3_5.1@4153.35,2380 4168.82,2395.48 4168.82,2682.64 4228.82,2742.64 4713.54,2742.64 4747.67,2708.51 J5_5.5@4747.67,2562.88
  Bottom Layer w40: D8_5.1@4195.35,2389.43 4163.35,2421.44 4163.35,2690 4223.35,2750 4706.18,2750 4747.67,2708.51 J5_5.5@4747.67,2562.88
IGBT_G: C16.1 D10.1 J5.2 Q2.3 R12.2 R15.1 R23.2 R24.2 R26.2 R28.2 | length 2256.4
  Top Layer w30: R15.1@639.33,1600.59 607.68,1632.24 607.68,1880.04 R23.2@700.3,1966.1 ; 794.69,2021.88 R24.2@850.46,1966.1
  Top Layer w35: R15.1@639.33,1600.59 725.16,1600.59 753.35,1572.4 Q2.3@766.69,1572.4 ; R23.2@682.48,1966.1 R23.2@700.3,1966.1
  Top Layer w50: J5.2@627.68,2562.87 627.68,2497.56 R12.2@615.12,2485 658.54,2485 788.74,2354.8 794.69,2354.8 794.69,2021.88
  Top Layer w120: R23.2@700.3,1966.1 711.63,1966.1 773.63,1966.1 R24.2@842.15,1966.1
  Bottom Layer w60: J5.2@627.68,2562.87 627.68,2477.87 678.76,2477.87 742.68,2413.95 742.68,2400
  Bottom Layer w70: 767.68,1978.74 771.61,1974.8
  Bottom Layer w90: R26.2@742.68,1978.74 742.68,2400
  Bottom Layer w120: R26.2@699.06,1974.8 771.61,1974.8 826.18,1974.8 R28.2@842.09,1974.8
  other v1: 713.79,1924.76 743.19,1924.76 773.63,1924.76 802.53,1924.76 826.18,1924.76 855.04,1924.76
IGBT_G_1: C16_1.1 D10_1.1 J5_1.2 Q2_1.3 R12_1.2 R15_1.1 R23_1.2 R24_1.2 R26_1.2 R28_1.2 | length 2174.7
  Top Layer w30: R15_1.1@1399.33,1600.59 1367.67,1632.25 1367.67,1880.04 R23_1.2@1460.3,1966.1 ; 1548.74,2027.83 R24_1.2@1610.46,1966.1
  Top Layer w35: R15_1.1@1399.33,1600.59 1485.15,1600.59 1513.34,1572.4 Q2_1.3@1526.69,1572.4 ; R23_1.2@1442.48,1966.1 R23_1.2@1460.3,1966.1
  Top Layer w50: R12_1.2@1397.67,2491.06 J5_1.2@1397.67,2562.88 ; R12_1.2@1407.67,2491.06 1548.74,2350 1548.74,2027.83
  Top Layer w120: R23_1.2@1460.3,1966.1 1533.63,1966.1 R24_1.2@1602.14,1966.1
  Bottom Layer w50: J5_1.2@1397.67,2562.88 1397.67,2501.06 1502.67,2396.06 1502.67,2390
  Bottom Layer w70: 1527.67,1978.74 1531.61,1974.81
  Bottom Layer w90: R26_1.2@1502.67,1978.74 1502.67,2390
  Bottom Layer w120: R26_1.2@1459.05,1974.81 1531.61,1974.81 1586.18,1974.81 R28_1.2@1602.08,1974.81
  other v1: 1473.79,1924.77 1503.18,1924.77 1533.63,1924.77 1562.53,1924.77 1586.18,1924.77 1615.04,1924.77
IGBT_G_2: C16_2.1 D10_2.1 J5_2.2 Q2_2.3 R12_2.2 R15_2.1 R23_2.2 R24_2.2 R26_2.2 R28_2.2 | length 2124.1
  Top Layer w30: R15_2.1@2159.33,1600.59 2127.68,1632.24 2127.68,1880.04 R23_2.2@2220.3,1966.1 ; 2314.68,2021.88 R24_2.2@2370.46,1966.1
  Top Layer w35: R15_2.1@2159.33,1600.59 2245.16,1600.59 2273.35,1572.4 Q2_2.3@2286.69,1572.4 ; R23_2.2@2202.48,1966.1 R23_2.2@2220.3,1966.1
  Top Layer w50: J5_2.2@2227.68,2562.87 2227.68,2474.16 2227.68,2450 2227.68,2408.93 2314.68,2321.93 2314.68,2021.88
  Top Layer w120: R23_2.2@2220.3,1966.1 2231.63,1966.1 2293.63,1966.1 R24_2.2@2362.15,1966.1
  Bottom Layer w60: C16_2.1@2228.35,2494.92 J5_2.2@2228.35,2562.87 ; C16_2.1@2228.53,2480 2228.53,2420 2251.41,2397.13 2265.27,2397.13 2265.27,2397.99
  Bottom Layer w70: 2287.68,1978.74 2291.61,1974.8 ; 2290.27,1975.86 2291.33,1974.8 2294.21,1971.93
  Bottom Layer w90: R26_2.2@2265.27,1975.86 2265.27,2397.13
  Bottom Layer w120: R26_2.2@2219.05,1974.8 2291.33,1974.8 2291.61,1974.8 2322.53,1974.8 R28_2.2@2362.09,1974.8
  other v1: 2233.79,1924.76 2263.19,1924.76 2293.63,1924.76 2322.53,1924.76 2346.18,1924.76 2375.04,1924.76
IGBT_G_3: C16_3.1 D10_3.1 J5_3.2 Q2_3.3 R12_3.2 R15_3.1 R23_3.2 R24_3.2 R26_3.2 R28_3.2 | length 2167.8
  Top Layer w30: R15_3.1@2919.33,1600.59 2887.68,1632.24 2887.68,1880.04 R23_3.2@2980.3,1966.1 ; 3074.69,2021.88 R24_3.2@3130.46,1966.1
  Top Layer w35: R15_3.1@2919.33,1600.59 3005.16,1600.59 3033.35,1572.4 Q2_3.3@3046.69,1572.4 ; R23_3.2@2962.48,1966.1 R23_3.2@2980.3,1966.1
  Top Layer w50: J5_3.2@2927.68,2562.87 2927.68,2475.67 3074.69,2328.66 3074.69,2021.88
  Top Layer w120: R23_3.2@2980.3,1966.1 3053.64,1966.1 R24_3.2@3122.15,1966.1
  Bottom Layer w60: C16_3.1@2928.35,2482.99 J5_3.2@2928.35,2562.87 ; C16_3.1@2948.35,2482.99 3028.35,2402.99 3028.35,2402.13
  Bottom Layer w70: 3047.68,1978.74 3051.61,1974.8 ; 3053.35,1980.86 3057.28,1976.93
  Bottom Layer w90: R26_3.2@3028.35,1980.86 3028.35,2402.13
  Bottom Layer w120: R26_3.2@2979.06,1974.8 3051.61,1974.8 3106.18,1974.8 R28_3.2@3122.09,1974.8
  other v1: 2993.79,1924.76 3023.19,1924.76 3053.64,1924.76 3082.53,1924.76 3106.18,1924.76 3135.04,1924.76
IGBT_G_4: C16_4.1 D10_4.1 J5_4.2 Q2_4.3 R12_4.2 R15_4.1 R23_4.2 R24_4.2 R26_4.2 R28_4.2 | length 2122
  Top Layer w30: R15_4.1@3679.33,1600.59 3647.68,1632.24 3647.68,1880.04 R23_4.2@3740.3,1966.1 ; 3834.68,2021.88 R24_4.2@3890.46,1966.1
  Top Layer w35: R15_4.1@3679.33,1600.59 3765.16,1600.59 3793.35,1572.4 Q2_4.3@3806.69,1572.4 ; R23_4.2@3722.48,1966.1 R23_4.2@3740.3,1966.1
  Top Layer w50: 3747.68,2407.87 3834.68,2320.87 3834.68,2021.88
  Top Layer w60: 3747.68,2407.87 J5_4.2@3747.68,2562.87
  Top Layer w120: R23_4.2@3740.3,1966.1 3813.63,1966.1 R24_4.2@3882.15,1966.1
  Bottom Layer w60: J5_4.2@3742.68,2562.87 3742.68,2447.99 3787.68,2402.99
  Bottom Layer w70: 3807.68,1978.74 3811.61,1974.8
  Bottom Layer w90: R26_4.2@3787.68,1980.86 3787.68,2402.12
  Bottom Layer w120: R26_4.2@3739.05,1974.8 3811.61,1974.8 3866.18,1974.8 R28_4.2@3882.09,1974.8
  other v1: 3753.79,1924.76 3783.19,1924.76 3813.63,1924.76 3842.53,1924.76 3866.18,1924.76 3895.04,1924.76
IGBT_G_5: C16_5.1 D10_5.1 J5_5.2 Q2_5.3 R12_5.2 R15_5.1 R23_5.2 R24_5.2 R26_5.2 R28_5.2 | length 2151.4
  Top Layer w30: R15_5.1@4439.33,1600.6 4407.67,1632.25 4407.67,1880.05 R23_5.2@4500.3,1966.11 ; 4594.68,2021.89 R24_5.2@4650.46,1966.11
  Top Layer w35: R15_5.1@4439.33,1600.6 4525.15,1600.6 4553.34,1572.41 Q2_5.3@4566.69,1572.41 ; R23_5.2@4482.48,1966.11 R23_5.2@4500.3,1966.11
  Top Layer w50: 4588.74,2335 4594.68,2329.06 4594.68,2021.89
  Top Layer w60: J5_5.2@4447.67,2562.88 4447.67,2476.81 4582.24,2342.24
  Top Layer w120: R23_5.2@4500.3,1966.11 4573.63,1966.11 R24_5.2@4642.14,1966.11
  Bottom Layer w60: C16_5.1@4447.67,2483 J5_5.2@4447.67,2562.88 ; 4467.67,2483 4547.67,2403
  Bottom Layer w70: 4567.67,1978.74 4571.61,1974.81
  Bottom Layer w90: R26_5.2@4547.67,1980.87 4547.67,2402.13
  Bottom Layer w120: R26_5.2@4499.05,1974.81 4571.61,1974.81 4626.18,1974.81 R28_5.2@4642.08,1974.81
  other v1: 4513.79,1924.77 4543.19,1924.77 4573.63,1924.77 4602.53,1924.77 4626.18,1924.77 4655.04,1924.77
IN+_A: J1.15 PWM_1.1 R17_4.1 R19_5.1 | length 5015.7
  Ground w20: J1.15@5733.35,2362.88 5784.57,2414.1 5951.11,2414.1 5984.47,2380.74 5984.47,2320
  Ground w35: PWM_1.1@4138.35,400.16 4138.35,265 4183.35,220 5417.87,220 5535.37,337.5 5770.85,337.5 5880,446.65 5880,1809.15 5984.47,1913.63 5984.47,2320
  Bottom Layer w6: R19_5.1@4476.73,387.37 R19_5.1@4476.73,400.16
  Bottom Layer w10: PWM_1.1@4142.23,379.49 PWM_1.1@4150.11,387.37
  Bottom Layer w35: R17_4.1@3775.79,388.35 PWM_1.1@4133.38,388.35 ; PWM_1.1@4142.23,379.49 PWM_1.1@4133.38,388.35 ; R19_5.1@4476.73,400.16 4445.17,400.16 4420.33,425 4190.26,425 4153.61,388.35 PWM_1.1@4133.38,388.35
IN+_B: J1.14 PWM_3.1 R17_2.1 R19_3.1 | length 5756.6
  Top Layer w30: v2(2968.35,293.46) v2(3138.35,293.46)
  Bottom Layer w6: R19_3.1@2956.73,387.36 R19_3.1@2956.73,400.16
  Bottom Layer w10: PWM_3.1@2622.24,379.49 PWM_3.1@2630.11,387.36
  Bottom Layer w20: 5581,2310 5582,2311 5582,2489 5606,2513 5683.23,2513 J1.14@5733.35,2462.88
  Bottom Layer w30: R17_2.1@2255.79,388.35 PWM_3.1@2607.36,388.35 ; PWM_3.1@2630.11,387.36 2668.35,387.36 ; 2667.36,388.35 2668.35,387.36 ; R19_3.1@2956.73,387.36 2936.54,387.36 ; v2(2968.35,293.46) 2968.35,355.55 2936.54,387.36 ; v2(3138.35,293.46) 3391.81,293.46 3438.58,340.24 3661.34,340.24 3718.75,282.82 4199.45,282.82 4246.63,330 4369.04,330 4416.22,282.82 5346.17,282.82 5415,351.65 5415,456.57 5533.35,574.92 5533.35,2262.35 5581,2310 ; 2668.35,387.36 2936.54,387.36
IN+_C: J1.16 PWM_5.1 R17.1 R19_1.1 | length 7551.5
  Top Layer w20: J1.16@5633.35,2562.88 5683.35,2512.88 5683.35,2333.35
  Top Layer w25: v2(1102.23,215) 1107.47,209.77 3328.11,209.77 3343.35,225 3968.35,225 3993.35,200 5174.88,200 5260.29,285.4 5260.29,1605.29 5490,1835 5490,2140 5683.35,2333.35
  Bottom Layer w25: v2(1102.23,215) PWM_5.1@1102.23,379.49
  Bottom Layer w30: R17.1@735.79,388.35 1102.23,388.35 1435.75,388.35 R19_1.1@1436.73,387.36
IN-_A: J1.13 PWM_2.1 R17_5.1 R19_4.1 | length 4624
  Bottom Layer w6: R19_4.1@3716.73,387.36 R19_4.1@3716.73,400.16
  Bottom Layer w10: PWM_2.1@3382.24,379.49 PWM_2.1@3390.11,387.36
  Bottom Layer w20: 5483,2303.57 5483,2595 5508,2620 5676.23,2620 J1.13@5733.35,2562.88
  Bottom Layer w30: PWM_2.1@3390.11,387.36 R19_4.1@3716.73,387.36 3716.73,364.68 3749.81,331.6 4174.95,331.6 4218.35,375 4393.35,375 4436.18,332.17 4553.35,332.17 ; R17_5.1@4553.35,364.29 R17_5.1@4553.35,389.63 ; R17_5.1@4554.26,383.19 4554.26,333.09 4553.35,332.17 ; 5160.51,332.17 4553.35,332.17
  Bottom Layer w35: 5160.51,332.17 5315,486.65 5315,1708.23 5473,1866.23 5473,2293.57 5483,2303.57
IN-_B: J1.18 PWM_4.1 R17_3.1 R19_2.1 | length 6387.7
  Bottom Layer w6: R19_2.1@2196.73,387.36 R19_2.1@2196.73,400.16
  Bottom Layer w10: PWM_4.1@1862.24,379.49 PWM_4.1@1870.11,387.36
  Bottom Layer w20: 5633.35,2292.65 J1.18@5633.35,2362.88
  Bottom Layer w25: R19_2.1@2196.73,387.36 2196.73,204.84 2283.7,117.87 2284.45,118.62 3028.35,118.62 ; R17_3.1@3015.79,388.35 3028.35,375.79 3028.35,118.62 ; 5633.35,2292.65 5588.35,2247.65 5588.35,554.88 5462.13,428.66 5462.13,182.13 5398.62,118.62 3028.35,118.62
  Bottom Layer w30: PWM_4.1@1870.11,387.36 R19_2.1@2196.73,387.36
IN-_C: J1.17 PWM_6.1 R17_1.1 R19.1 | length 8195.1
  Bottom Layer w6: R19.1@676.73,387.36 R19.1@676.73,400.16
  Bottom Layer w10: PWM_6.1@342.24,379.49 PWM_6.1@350.11,387.36
  Bottom Layer w20: J1.17@5633.35,2462.88 5683.35,2412.88 5683.35,2277.65
  Bottom Layer w25: R19.1@676.73,387.36 676.73,151.61 743.35,85 1495.78,85 ; 1495.78,84.25 1496.53,84.25 1495.78,85 ; R17_1.1@1495.78,388.35 1495.78,85 ; 1496.53,79.25 5447.6,79.25 5454.25,79.25 5515,140 5515,410.02 5635,530.02 5635,2229.31 5683.35,2277.65
  Bottom Layer w30: PWM_6.1@350.11,387.36 R19.1@676.73,387.36
ISO_GND: C2.1 C3.1 C4.1 C11.2 C12.2 C16.2 C17.2 C18.2 C19.2 C29.2 C30.1 D5.2 J4.2 J5.1 J7.2 R12.1 U1.21 U1.22 U1.23 U1.25 U1.28 | length 4089
  Top Layer w16: v1(699.06,1260) 701.34,1257.72 U1.25@701.34,1165.91
  Top Layer w17: U1.28@624.57,1165.91 v1(624.57,1216.1) v1(624.57,1235.79)
  Top Layer w40: C3.1@365.39,1411.93 410.04,1411.93 422.28,1399.69 422.28,1393.27 ; J5.1@527.68,2562.87 527.68,2505.28 R12.1@550.04,2482.91 ; C19.2@716.1,1375.55 748.58,1375.55 748.58,1372.6
  Top Layer w70: J7.2@83.03,2565 83.03,1559.92 222.13,1420.83 C3.1@395,1420.83
  Power w17: 624.57,1177.05 v1(624.57,1216.1) v1(624.57,1235.79)
  Power w18: v1(432.35,1389.04) v1(412.8,1389.04) v1(412.8,1320) v1(434.41,1320) 450.74,1320 470.74,1300 470.74,1195.76
  Power w20: 470.74,1195.76 489.45,1177.05 624.57,1177.05 742.05,1177.05 760.01,1195.01 760.01,1215.37 v1(769.49,1224.85) v1(794.73,1224.85)
  Ground w17: v1(624.57,1216.1) v1(624.57,1235.79)
  Ground w70: 527.68,2344.88 J5.1@527.68,2562.87 ; 735.63,2298.78 794.69,2239.72 J4.2@873.43,2239.72
  Bottom Layer w17: C17.2@586.18,1172.8 612.33,1129.49 745.63,1129.49 C18.2@783.03,1166.89 ; C17.2@593.07,1172.8 593.07,1184.61 v1(624.57,1216.1) v1(624.57,1235.79) v1@625.28,1236.5 ; C17.2@594.84,1161.38 C17.2@594.84,1163.78
  Bottom Layer w20: 777.13,1203.18 769.49,1210.82 v1(769.49,1224.85) v1(794.73,1224.85) C18.2@794.73,1175.86
  Bottom Layer w35: C11.2@411.77,1280 422.41,1290.64 422.41,1345.51 C12.2@416,1351.93 418.7,1354.63 418.7,1429.83 438.07,1449.19 C2.1@438.07,1472.01 ; C2.1@440.35,1456.22 440.35,1551.09 447.87,1558.6 447.87,1629.49 447.49,1629.86 447.49,1727.91
  Bottom Layer w40: C4.1@777.05,1507.36 752.52,1482.83 v1(752.52,1383.43) 752.52,1366.88 755.66,1363.74 841.93,1363.74 C29.2@843.9,1365.71 ; 777.13,1203.18 C18.2@777.13,1175.86 777.13,1166.89 C18.2@783.03,1166.89
  Bottom Layer w50: J5.1@527.68,2562.87 527.68,2490.95 C16.2@540.75,2477.87
  other v1: 755.66,1362 437.56,1735.75 457.24,1735.75
ISO_GND_1: C2_1.1 C3_1.1 C4_1.1 C11_1.2 C12_1.2 C16_1.2 C17_1.2 C18_1.2 C19_1.2 C29_1.2 C30_1.1 D5_1.2 J4_1.2 J5_1.1 R12_1.1 U1_1.21 U1_1.22 U1_1.23 U1_1.25 U1_1.28 | length 2732.2
  Top Layer w16: U1_1.25@1461.33,1165.91 v1@1461.33,1257.72
  Top Layer w17: U1_1.28@1384.56,1165.91 v1(1384.56,1216.1) v1(1384.56,1235.79)
  Top Layer w40: C3_1.1@1128.08,1416.93 1165.04,1416.93 1182.28,1399.69 ; 1182.28,1393.27 1182.28,1399.69 ; 1183.76,1398.2 1182.28,1399.69 ; C19_1.2@1476.1,1375.55 1508.58,1375.55 1508.58,1372.6
  Top Layer w50: J5_1.1@1297.67,2563.82 1297.67,2499.02 1311.69,2485 R12_1.1@1331.85,2485
  Power w17: 1384.56,1180 v1(1384.56,1216.1) v1(1384.56,1235.79)
  Power w18: v1(1192.34,1389.05) v1(1172.79,1389.05) 1172.79,1320 1210.74,1320 1230.74,1300 1230.74,1195.76
  Power w20: 1230.74,1195.76 1249.44,1177.05 1502.04,1177.05 1520,1195.01 1520,1215.37 v1(1529.48,1224.85) v1(1554.72,1224.85)
  Ground w17: v1(1384.56,1216.1) v1(1384.56,1235.79)
  Ground w70: 1297.67,2342 J5_1.1@1297.67,2563.82 ; 1495.63,2298.78 1554.68,2239.73 J4_1.2@1633.42,2239.73
  Bottom Layer w17: C17_1.2@1346.18,1172.8 C17_1.2@1356.18,1158.86 ; C17_1.2@1353.07,1172.8 1353.07,1184.61 v1(1384.56,1216.1) v1(1384.56,1235.79) v1@1385.28,1236.51 ; C17_1.2@1356.18,1156.46 C17_1.2@1356.18,1158.86 ; C18_1.2@1543.03,1166.89 1505.63,1129.49 1375.55,1129.49 C17_1.2@1356.18,1158.86
  Bottom Layer w20: 1537.12,1203.18 1529.48,1210.82 v1(1529.48,1224.85) v1(1554.72,1224.85) C18_1.2@1554.72,1175.87
  Bottom Layer w35: C11_1.2@1178.7,1282.88 1178.7,1378.95 1188.79,1389.05 1188.79,1439.93 1198.06,1449.2 C2_1.1@1198.06,1472.01 ; C2_1.1@1200.35,1456.22 1200.35,1566.12 1207.86,1558.61 1207.86,1629.49 1207.49,1629.87 1207.49,1727.92
  Bottom Layer w40: C4_1.1@1537.04,1507.36 1512.52,1482.84 v1(1512.52,1383.43) 1512.52,1366.88 1515.65,1363.74 1601.93,1363.74 C29_1.2@1603.89,1365.71 ; 1537.12,1203.18 C18_1.2@1537.12,1175.87 1537.12,1166.89 C18_1.2@1543.03,1166.89
  Bottom Layer w50: J5_1.1@1297.67,2562.88 1297.67,2499.84 C16_1.2@1317.52,2480
  other v1: 1459.05,1260 1172,1320 1193.62,1320 1515.65,1362 1197.55,1735.75 1217.24,1735.75
ISO_GND_2: C2_2.1 C3_2.1 C4_2.1 C11_2.2 C12_2.2 C16_2.2 C17_2.2 C18_2.2 C19_2.2 C29_2.2 C30_2.1 D5_2.2 J4_2.2 J5_2.1 R12_2.1 U1_2.21 U1_2.22 U1_2.23 U1_2.25 U1_2.28 | length 2720.8
  Top Layer w16: U1_2.25@2221.34,1165.91 v1@2221.34,1257.72
  Top Layer w17: U1_2.28@2144.57,1165.91 v1(2144.57,1216.1) v1(2144.57,1235.79)
  Top Layer w35: C3_2.1@1887.87,1416.93 1906.6,1398.2 1948.07,1398.2
  Top Layer w40: C19_2.2@2236.1,1375.55 2268.58,1375.55 2268.58,1372.6
  Top Layer w50: J5_2.1@2127.68,2562.87 2127.68,2524.36 R12_2.1@2157.04,2495
  Power w17: 2144.57,1180 v1(2144.57,1216.1) v1(2144.57,1235.79)
  Power w18: v1@1952.35,1389.04 1932.8,1389.04 1932.8,1320 1970.74,1320 1990.74,1300 1990.74,1195.76
  Power w20: 1990.74,1195.76 2009.45,1177.05 2262.05,1177.05 2280.01,1195.01 2280.01,1215.37 v1(2289.49,1224.85) v1(2314.73,1224.85)
  Ground w17: v1(2144.57,1216.1) v1(2144.57,1235.79)
  Ground w70: 2066.69,2344.88 2066.69,2502.83 J5_2.1@2127.68,2563.82 ; 2255.63,2298.78 2314.68,2239.72 J4_2.2@2393.43,2239.72
  Bottom Layer w17: C17_2.2@2106.18,1172.79 2107.51,1170.39 C17_2.2@2116.02,1155 ; C17_2.2@2113.07,1172.79 2113.07,1184.61 v1(2144.57,1216.1) v1(2144.57,1235.79) v1@2145.28,1236.5 ; 2116.02,1152.6 C17_2.2@2116.02,1155 ; C18_2.2@2303.03,1166.89 2265.63,1129.49 2135.55,1129.49 C17_2.2@2116.02,1155
  Bottom Layer w20: 2297.13,1203.18 2289.49,1210.82 v1(2289.49,1224.85) v1(2314.73,1224.85) C18_2.2@2314.73,1175.86
  Bottom Layer w35: C11_2.2@1933.35,1283.47 1942.41,1292.54 1942.41,1319.16 1942.41,1345.78 1936.26,1351.93 C12_2.2@1937.48,1353.15 ; C12_2.2@1938.7,1351.93 C12_2.2@1937.48,1353.15 ; C2_2.1@1958.07,1472.01 1958.07,1449.19 1945,1436.12 1945,1360.67 C12_2.2@1937.48,1353.15 ; C2_2.1@1960.35,1456.22 1960.35,1551.09 1967.87,1558.6 1967.87,1629.49 1967.49,1629.86 1967.49,1727.91
  Bottom Layer w40: C4_2.1@2297.05,1507.36 2272.52,1482.83 v1(2272.52,1383.42) 2272.52,1366.88 2275.66,1363.74 2361.93,1363.74 C29_2.2@2363.9,1365.71 ; 2297.13,1203.18 C18_2.2@2297.13,1175.86 2297.13,1166.89 C18_2.2@2303.03,1166.89
  Bottom Layer w50: C16_2.2@2127.68,2490.95 J5_2.1@2127.68,2562.87 ; C16_2.2@2127.9,2490.95 C16_2.2@2140.98,2477.87
  other v1: 2219.05,1260 1935.47,1319.16 1956.46,1318.8 2275.66,1362 1934.21,1389.05 1955.79,1389.05 1957.56,1735.75 1977.24,1735.75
